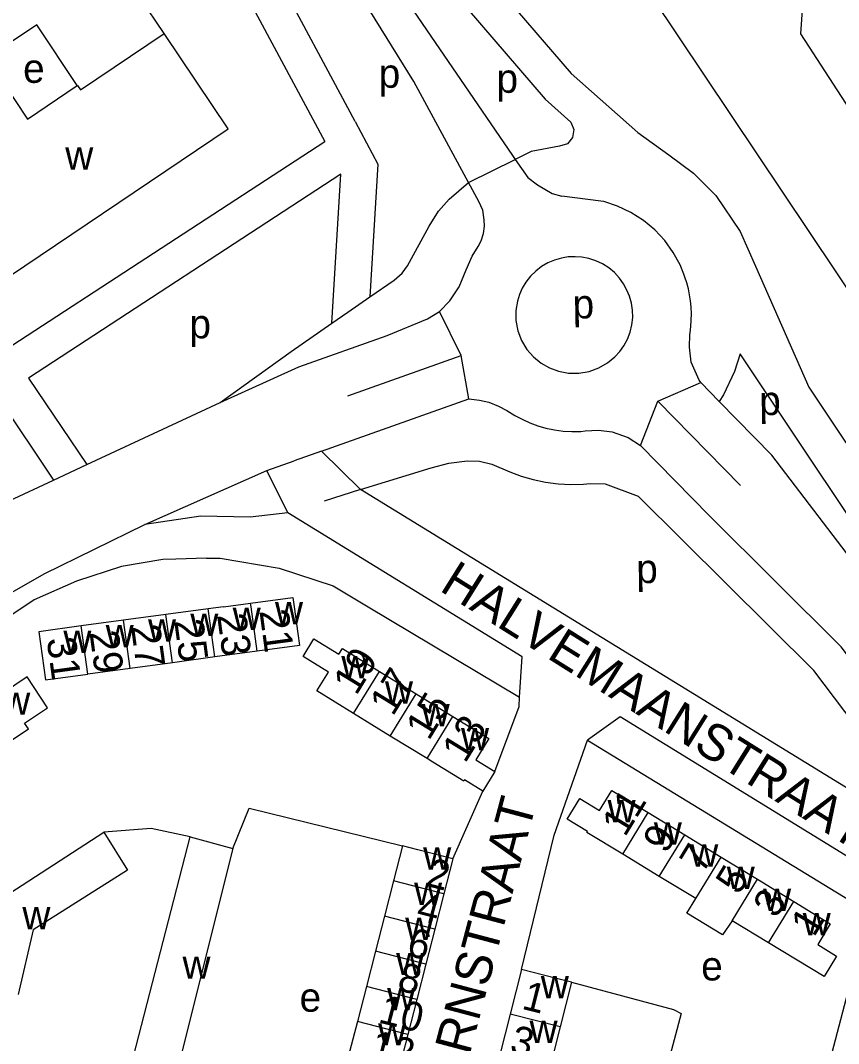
# Model space of a CAD drawing. Extents: x 158356 to 159894, y 383831 to 385260.
# Drawn here: x 159266.4 to 159379.2, y 384439.8 to 384580.8 of the extents above; entities that cross this region are included whole.
import ezdxf

# ---------------------------------------------------------------- set-up
doc = ezdxf.new("R2010")
doc.units = 0
for name, color, linetype in [('BLT_Basislijn', 7, 'Continuous'), ('BLT_Bebouwing', 7, 'Continuous'), ('BLT_Centroide', 7, 'Continuous'), ('BLT_Huisnummer', 7, 'Continuous'), ('BLT_Huisnummer_ tussenligend', 7, 'Continuous'), ('BLT_Onderdoorgang_en_onderverdeling', 7, 'Continuous'), ('BLT_Onderverdeling_panden', 7, 'Continuous'), ('BLT_Straatnaam', 7, 'Continuous'), ('BLT_Vlakafsluiter', 7, 'Continuous')]:
    doc.layers.add(name, color=color, linetype=linetype)

msp = doc.modelspace()

# ---------------------------------------------------------------- linework, layer by layer
at = {"layer": 'BLT_Basislijn'}
for p, q in [((159409.74, 384500), (159332.15, 384615.97)), ((159374.24, 384582.91), (159373.95, 384578.96)), ((159149.54, 384460.54), (159308.38, 384564.12)), ((159311.58, 384540.61), (159314.61, 384542.7)), ((159309.39, 384539.09), (159311.58, 384540.61)), ((159311.58, 384529.09), (159327.21, 384534.63)), ((159267.55, 384531.52), (159275.6, 384519.6)), ((159362.78, 384528.28), (159360.22, 384530.89)), ((159263.36, 384528.79), (159271.01, 384517.47)), ((159365.71, 384516.72), (159354.32, 384528.34)), ((159275.6, 384519.6), (159293.96, 384528.16)), ((159313.34, 384516.16), (159307.94, 384521.43)), ((159361.43, 384512.52), (159351.91, 384522.23)), ((159300.43, 384518.77), (159304.19, 384520.1)), ((159271.01, 384517.47), (159275.6, 384519.6)), ((159303.28, 384512.95), (159300.43, 384518.77)), ((159313.34, 384516.16), (159308.31, 384514.55)), ((159314.38, 384500), (159335.25, 384487.57)), ((159326.06, 384465.3), (159330.18, 384474.59)), ((159382.91, 384456.26), (159376.56, 384431.88))]:
    msp.add_line(p, q, dxfattribs=at)
for points in [[(159078.95, 384989.43), (159096.2, 384978.92), (159116.42, 384963.88), (159133.76, 384948.84), (159152.75, 384928.69), (159175.27, 384898.83), (159191.66, 384869.8), (159265.75, 384692.27), (159279.24, 384664.38), (159294.85, 384637.65), (159324.9, 384593.77), (159342.37, 384573.46), (159351.56, 384565.34), (159355.82, 384562.28)], [(159312.59, 384566.87), (159301.16, 384588.23), (159283.03, 384619.67)], [(159296.91, 384618.16), (159310.51, 384598.25), (159318.85, 384584.79), (159334.25, 384562.19), (159334.63, 384561.64)], [(159283.82, 384608.28), (159296.79, 384585.8), (159308.38, 384564.12)], [(159328.22, 384558.45), (159320.65, 384572.4), (159306.32, 384595.52), (159298.81, 384606.52)], [(159320.93, 384590.72), (159338.79, 384569.96), (159342.29, 384566.79), (159342.73, 384565.76), (159342.55, 384564.64), (159341.83, 384563.78), (159340.76, 384563.45), (159336.83, 384562.74), (159334.63, 384561.64)], [(159373.95, 384578.96), (159397.06, 384543.35), (159426.1, 384500)], [(159312.59, 384566.87), (159315.69, 384560.98), (159314.61, 384542.7)], [(159355.82, 384562.28), (159359.21, 384559.77), (159362.31, 384556.68), (159365.63, 384551.72), (159367.76, 384546.94), (159375.12, 384530.26), (159395.34, 384500)], [(159334.63, 384561.64), (159336.38, 384559.13), (159337.73, 384558.12), (159339.72, 384556.95), (159341.05, 384556.57)], [(159309.39, 384539.09), (159310.6, 384559.6), (159267.55, 384531.52)], [(159314.61, 384542.7), (159317.98, 384545.02), (159319.08, 384545.97), (159319.82, 384546.96), (159322.79, 384552.45), (159324.05, 384554.51), (159325.56, 384556.16), (159328.22, 384558.45)], [(159329.63, 384555.84), (159328.22, 384558.45)], [(159357.9, 384545.83), (159357.37, 384547.14), (159356.43, 384548.84), (159355.27, 384550.45), (159353.89, 384551.93), (159352.32, 384553.23), (159350.59, 384554.33), (159348.76, 384555.2), (159346.85, 384555.83), (159346.46, 384555.91), (159341.05, 384556.57)], [(159324.21, 384540.7), (159325.63, 384542.18), (159326.94, 384544.11), (159327.87, 384546.41), (159328.72, 384548.29), (159329.53, 384549.66), (159329.96, 384550.41), (159330.27, 384551.42), (159330.42, 384552.45), (159330.37, 384553.34), (159330.16, 384554.64), (159329.63, 384555.84)], [(159350.4, 384542.78), (159350.05, 384543.65), (159349.58, 384544.49), (159349, 384545.3), (159348.32, 384546.04), (159347.53, 384546.69), (159346.67, 384547.24), (159345.75, 384547.67), (159344.8, 384547.98), (159343.84, 384548.17), (159342.89, 384548.24), (159341.96, 384548.2), (159341.02, 384548.05), (159340.08, 384547.78), (159339.16, 384547.39), (159338.28, 384546.88), (159337.47, 384546.26), (159336.75, 384545.54), (159336.12, 384544.75), (159335.61, 384543.9), (159335.22, 384543.02), (159334.94, 384542.12)], [(159360.22, 384530.89), (159360.01, 384531.22), (159358.88, 384533.69), (159358.67, 384535.78), (159358.7, 384537.52), (159358.74, 384537.74), (159358.85, 384538.62), (159358.92, 384539.51), (159358.93, 384540.39), (159358.89, 384541.27), (159358.81, 384542.14), (159358.68, 384542.99), (159358.51, 384543.83), (159358.3, 384544.64), (159358.04, 384545.44), (159357.9, 384545.83)], [(159348.39, 384534.45), (159349.05, 384535.16), (159349.63, 384535.97), (159350.11, 384536.86), (159350.48, 384537.82), (159350.73, 384538.83), (159350.84, 384539.85), (159350.81, 384540.86), (159350.67, 384541.85), (159350.4, 384542.78)], [(159334.94, 384542.12), (159334.73, 384540.81), (159334.75, 384539.43), (159335.01, 384538.04), (159335.52, 384536.7), (159336.25, 384535.47), (159337.17, 384534.42), (159338.22, 384533.56), (159339.36, 384532.92), (159340.63, 384532.45), (159342, 384532.19), (159343.43, 384532.19), (159344.84, 384532.43), (159346.18, 384532.92), (159347.37, 384533.61), (159348.39, 384534.45)], [(159293.96, 384528.16), (159304.81, 384533.05), (159317.01, 384537.38), (159322.55, 384539.68), (159324.21, 384540.7)], [(159293.96, 384528.16), (159303.76, 384535.18), (159309.39, 384539.09)], [(159388.95, 384500), (159365.65, 384534.86), (159364.86, 384532.44), (159363.35, 384529.22), (159362.78, 384528.28)], [(159307.94, 384521.43), (159328.27, 384528.64)], [(159328.27, 384528.64), (159329.72, 384528.49), (159331.01, 384528.19), (159332.36, 384527.66), (159333.49, 384527.03), (159334.6, 384526.38), (159335.59, 384525.84), (159336.64, 384525.36), (159337.74, 384524.95), (159338.88, 384524.62), (159340.05, 384524.38), (159341.25, 384524.22), (159342.46, 384524.15), (159343.67, 384524.17), (159344.27, 384524.23), (159346.11, 384524.33), (159347.99, 384524.12), (159350.21, 384523.32), (159351.91, 384522.23)], [(159408.73, 384470.2), (159370, 384520.91), (159362.78, 384528.28)], [(159313.34, 384516.16), (159323.04, 384519.15), (159325.48, 384519.8), (159328, 384520.1), (159329.72, 384520.07), (159331.4, 384519.66), (159333.89, 384518.6), (159335.46, 384518.02), (159337.12, 384517.54), (159338.82, 384517.19), (159340.56, 384516.96), (159342.32, 384516.86), (159344.08, 384516.89), (159344.96, 384516.97), (159347.04, 384516.96), (159351.59, 384515.23)], [(159283.58, 384511.35), (159300.43, 384518.77)], [(159228.21, 384492.39), (159235.76, 384497.5), (159248.86, 384505.88), (159264.87, 384514.61), (159271.01, 384517.47)], [(159391.07, 384467.32), (159386, 384471.58), (159313.34, 384516.16)], [(159392.92, 384468.61), (159375.79, 384491.21), (159351.59, 384515.23)], [(159303.28, 384512.95), (159298.11, 384512.35), (159291.32, 384512.51), (159283.58, 384511.35)], [(159335.25, 384487.57), (159335.59, 384493.12), (159303.28, 384512.95)], [(159476.29, 384336.47), (159467.84, 384354.16), (159459.96, 384370.94), (159444.22, 384401.18), (159439.12, 384409.82), (159405.78, 384459.91), (159379.56, 384494.51), (159361.43, 384512.52)], [(159254.02, 384495.59), (159269.72, 384504.56), (159283.58, 384511.35)], [(159287.88, 384506.57), (159286.09, 384506.51), (159280.37, 384505.57), (159274.15, 384503.55), (159268.33, 384500.97)], [(159292.1, 384506.71), (159287.88, 384506.57)], [(159292.1, 384506.71), (159293.96, 384506.71), (159302.13, 384505.33), (159309.56, 384502.87), (159314.38, 384500)], [(159268.33, 384500.97), (159186.01, 384445.78)], [(159331.85, 384477.29), (159335.18, 384486.26), (159335.25, 384487.57)], [(159349.1, 384484.83), (159344.6, 384481.65)], [(159382.91, 384456.26), (159385.13, 384456.88), (159385.8, 384459.47), (159385.76, 384460.38), (159385.47, 384461.28), (159385.02, 384461.95), (159381.31, 384465.07), (159349.1, 384484.83)], [(159335.5, 384450.01), (159340.03, 384468.53), (159344.6, 384481.65)], [(159344.6, 384481.65), (159382.38, 384458.56), (159382.91, 384456.26)], [(159295.74, 384466.72), (159297.98, 384472.28), (159319.09, 384467.08)], [(159289.83, 384468.29), (159284.45, 384469.47), (159277.95, 384468.95)], [(159342.4, 384448.28), (159356.44, 384444.51), (159357.5, 384443.96), (159355.61, 384436.72)]]:
    msp.add_lwpolyline(points, dxfattribs=at)
at = {"layer": 'BLT_Bebouwing'}
for p, q in [((159286.26, 384578.98), (159277.4, 384592.14)), ((159294.43, 384500), (159298.17, 384500.51)), ((159286.5, 384498.93), (159280.66, 384498.14)), ((159292.34, 384499.72), (159286.5, 384498.93)), ((159294.43, 384500), (159292.34, 384499.72)), ((159280.66, 384498.14), (159274.83, 384497.36)), ((159293.23, 384493.09), (159287.39, 384492.3)), ((159299.07, 384493.88), (159293.23, 384493.09)), ((159287.39, 384492.3), (159281.56, 384491.52)), ((159281.56, 384491.52), (159275.72, 384490.73)), ((159315.94, 384491.11), (159321, 384488.01)), ((159321, 384488.01), (159326.06, 384484.9)), ((159317.43, 384482.2), (159312.37, 384485.3)), ((159322.49, 384479.09), (159317.43, 384482.2)), ((159331.85, 384477.29), (159330.18, 384474.59)), ((159352.99, 384471.65), (159358.01, 384468.58)), ((159262.9, 384459.21), (159277.95, 384468.95)), ((159281.51, 384436.05), (159289.83, 384468.29)), ((159289.83, 384468.29), (159295.74, 384466.72)), ((159358.01, 384468.58), (159363.03, 384465.52)), ((159295.74, 384466.72), (159287.58, 384434.32)), ((159319.09, 384467.08), (159317.85, 384462.24)), ((159326.06, 384465.3), (159324.82, 384460.46)), ((159354.51, 384462.85), (159349.48, 384465.9)), ((159363.03, 384465.52), (159368.05, 384462.46)), ((159317.85, 384462.24), (159316.61, 384457.4)), ((159359.53, 384459.79), (159354.51, 384462.85)), ((159368.05, 384462.46), (159373.06, 384459.4)), ((159324.82, 384460.46), (159323.57, 384455.61)), ((159316.61, 384457.4), (159315.37, 384452.55)), ((159369.58, 384453.69), (159364.56, 384456.74)), ((159323.57, 384455.61), (159322.33, 384450.77)), ((159315.37, 384452.55), (159314.13, 384447.71)), ((159322.33, 384450.77), (159321.09, 384445.92)), ((159335.5, 384450.01), (159333.95, 384443.86)), ((159342.4, 384448.28), (159340.86, 384442.12)), ((159321.09, 384445.92), (159319.85, 384441.08)), ((159312.89, 384442.86), (159311.64, 384438.02)), ((159319.85, 384441.08), (159318.61, 384436.23))]:
    msp.add_line(p, q, dxfattribs=at)
for points in [[(159274.28, 384571.81), (159268.71, 384580.2), (159261.8, 384575.58)], [(159259.7, 384548.43), (159262.64, 384544.05), (159295.1, 384565.85), (159286.26, 384578.98)], [(159261.8, 384575.58), (159267.41, 384567.17), (159274.28, 384571.81)], [(159298.17, 384500.51), (159304.01, 384501.29), (159304.18, 384500)], [(159304.18, 384500), (159304.68, 384496.34), (159304.9, 384494.67), (159299.07, 384493.88)], [(159274.83, 384497.36), (159268.99, 384496.57), (159269.66, 384491.61), (159269.89, 384489.94), (159275.72, 384490.73)], [(159312.37, 384485.3), (159307.31, 384488.41), (159308.9, 384490.99), (159305.4, 384493.14), (159306.89, 384495.57), (159310.33, 384493.46), (159310.82, 384494.26), (159315.94, 384491.11)], [(159262.63, 384479.91), (159267.56, 384483.19), (159267.02, 384483.99), (159270.19, 384486.1), (159267.37, 384490.34), (159263.96, 384488.07), (159263.48, 384488.79), (159258.79, 384485.67)], [(159326.06, 384484.9), (159331.03, 384481.85), (159329.22, 384478.9), (159331.85, 384477.29)], [(159330.18, 384474.59), (159327.65, 384476.14), (159327.55, 384475.99), (159323.29, 384478.6), (159322.49, 384479.09)], [(159349.48, 384465.9), (159344.53, 384468.9), (159344.62, 384469.05), (159341.81, 384470.76), (159343.54, 384473.6), (159346.28, 384471.93), (159347.98, 384474.71), (159352.99, 384471.65)], [(159277.95, 384468.95), (159281.21, 384463.72), (159268.18, 384455.49), (159266.14, 384446.58)], [(159326.06, 384465.3), (159321.21, 384466.54), (159319.09, 384467.08)], [(159364.56, 384456.74), (159363.2, 384454.81), (159358.31, 384457.79), (159359.53, 384459.79)], [(159373.06, 384459.4), (159378.08, 384456.34), (159376.34, 384453.48), (159378.94, 384451.89), (159377.21, 384449.06), (159369.58, 384453.69)], [(159342.4, 384448.28), (159340.35, 384448.79), (159335.5, 384450.01)], [(159314.13, 384447.71), (159312.89, 384442.86)], [(159333.95, 384443.86), (159332.59, 384438.44), (159332.77, 384438.39), (159331.77, 384434.4)], [(159340.86, 384442.12), (159339.48, 384436.65), (159338.24, 384436.96), (159337.25, 384433.02)]]:
    msp.add_lwpolyline(points, dxfattribs=at)
at = {"layer": 'BLT_Onderdoorgang_en_onderverdeling'}
msp.add_lwpolyline([(159274.28, 384571.81), (159274.32, 384571.84), (159274.72, 384571.25), (159286.26, 384578.98)], dxfattribs=at)
at = {"layer": 'BLT_Onderverdeling_panden'}
for p, q in [((159298.24, 384500), (159298.17, 384500.51)), ((159287.39, 384492.3), (159286.5, 384498.93)), ((159293.23, 384493.09), (159292.34, 384499.72)), ((159299.07, 384493.88), (159298.24, 384500)), ((159275.72, 384490.73), (159274.83, 384497.36)), ((159281.56, 384491.52), (159280.66, 384498.14)), ((159312.37, 384485.3), (159315.94, 384491.11)), ((159317.43, 384482.2), (159321, 384488.01)), ((159322.49, 384479.09), (159326.06, 384484.9)), ((159349.48, 384465.9), (159352.99, 384471.65)), ((159354.51, 384462.85), (159358.01, 384468.58)), ((159359.53, 384459.79), (159363.03, 384465.52)), ((159324.82, 384460.46), (159317.85, 384462.24)), ((159364.56, 384456.74), (159368.05, 384462.46)), ((159369.58, 384453.69), (159373.06, 384459.4)), ((159323.57, 384455.61), (159316.61, 384457.4)), ((159322.33, 384450.77), (159315.37, 384452.55)), ((159321.09, 384445.92), (159314.13, 384447.71)), ((159340.86, 384442.12), (159333.95, 384443.86)), ((159319.85, 384441.08), (159312.89, 384442.86))]:
    msp.add_line(p, q, dxfattribs=at)
at = {"layer": 'BLT_Vlakafsluiter'}
for p, q in [((159328.22, 384558.45), (159334.63, 384561.64)), ((159327.21, 384534.63), (159324.21, 384540.7)), ((159328.27, 384528.64), (159327.21, 384534.63)), ((159354.32, 384528.34), (159360.22, 384530.89)), ((159351.91, 384522.23), (159354.32, 384528.34)), ((159307.94, 384521.43), (159304.19, 384520.1))]:
    msp.add_line(p, q, dxfattribs=at)

# ---------------------------------------------------------------- texts
at = {"layer": 'BLT_Centroide'}
for s, p in [('e', (159266.81, 384572.19)), ('p', (159315.82, 384571.51)), ('p', (159332.06, 384570.82)), ('w', (159272.62, 384560.23)), ('p', (159289.73, 384536.99)), ('w', (159301.53, 384497.59)), ('w', (159289.86, 384496)), ('w', (159295.7, 384496.8)), ('w', (159278.19, 384494.44)), ('w', (159284.03, 384495.22)), ('w', (159272.36, 384493.66)), ('w', (159310.67, 384490.17)), ('w', (159316.69, 384486.66)), ('w', (159263.94, 384485.12)), ('w', (159321.75, 384483.55)), ('w', (159327.17, 384480.22)), ('w', (159347.37, 384470.31)), ('w', (159353.75, 384467.25)), ('w', (159321.96, 384463.78)), ('w', (159358.77, 384464.19)), ('w', (159363.8, 384461.14)), ('w', (159320.71, 384458.94)), ('w', (159368.81, 384458.08)), ('w', (159266.71, 384455.56)), ('w', (159374.27, 384454.75)), ('w', (159319.48, 384454.09)), ('w', (159318.23, 384449.25)), ('w', (159288.78, 384448.75)), ('e', (159360.28, 384448.52)), ('w', (159338.17, 384446.06)), ('e', (159304.92, 384444.21)), ('w', (159316.99, 384444.41)), ('w', (159315.74, 384439.56)), ('w', (159336.62, 384439.91))]:
    msp.add_text(s, height=4, dxfattribs=at).set_placement(p)
for p in [(159342.58, 384539.71), (159368.3, 384526.39), (159351.35, 384503.24)]:
    msp.add_text('p', height=4, rotation=1, dxfattribs=at).set_placement(p)
at = {"layer": 'BLT_Huisnummer'}
for s, rotation, p in [('21', 277.6802, (159299.38, 384499.43)), ('25', 277.6802, (159287.63, 384498.08)), ('31', 277.6802, (159270.05, 384495.58)), ('19', 58.4624, (159312.73, 384487.66)), ('13', 58.462, (159327.74, 384478.33)), ('11', 58.6102, (159349.77, 384468.17)), ('2', 345.6236, (159322.15, 384461.6)), ('5', 58.6102, (159365.46, 384460.18)), ('1', 58.6102, (159375.82, 384454.38)), ('6', 345.6236, (159319.51, 384452.02)), ('1', 345.8779, (159335.4, 384444.65)), ('10', 345.6236, (159315.63, 384442.77))]:
    msp.add_text(s, height=4, rotation=rotation, dxfattribs=at).set_placement(p)
at = {"layer": 'BLT_Huisnummer_ tussenligend'}
for s, rotation, p in [('23', 277.6802, (159293.54, 384498.87)), ('27', 277.6802, (159281.67, 384497.33)), ('29', 277.6802, (159275.95, 384496.5)), ('17', 58.462, (159317.77, 384484.8)), ('15', 58.462, (159322.73, 384481.45)), ('9', 58.6102, (159355.42, 384465.85)), ('7', 58.6102, (159360.49, 384463.12)), ('3', 58.6102, (159370.62, 384456.95)), ('4', 345.6236, (159320.84, 384456.89)), ('8', 345.6236, (159318.22, 384447.24)), ('12', 345.6236, (159314.41, 384437.88)), ('3', 345.8779, (159333.73, 384438.56))]:
    msp.add_text(s, height=4, rotation=rotation, dxfattribs=at).set_placement(p)
at = {"layer": 'BLT_Straatnaam'}
for s, height, rotation, p in [('HALVEMAANSTRAAT', 5, 327.9266, (159324.06, 384502.31)), ('VUURDOORNSTRAAT', 4.9999, 75.1256, (159319.57, 384405.09))]:
    msp.add_text(s, height=height, rotation=rotation, dxfattribs=at).set_placement(p)

doc.saveas('drawing.dxf')
